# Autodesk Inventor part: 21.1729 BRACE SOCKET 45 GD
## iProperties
Created: 2007-04
Part Number: 21.1729 BRACE SOCKET 45 GD
Document SubType Name: Modeling
Designer: Andy Moles
Material: Aluminum-6061
Density: 2.71 g/cm^3
Author: Andy Moles
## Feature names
1. Extrusion1
2. Extrusion2
3. Extrusion3
4. Extrusion4
5. Extrusion5
6. Extrusion6
7. Extrusion7
8. Extrusion8
9. Extrusion9
10. Extrusion10
11. Extrusion12
12. Mirror1
